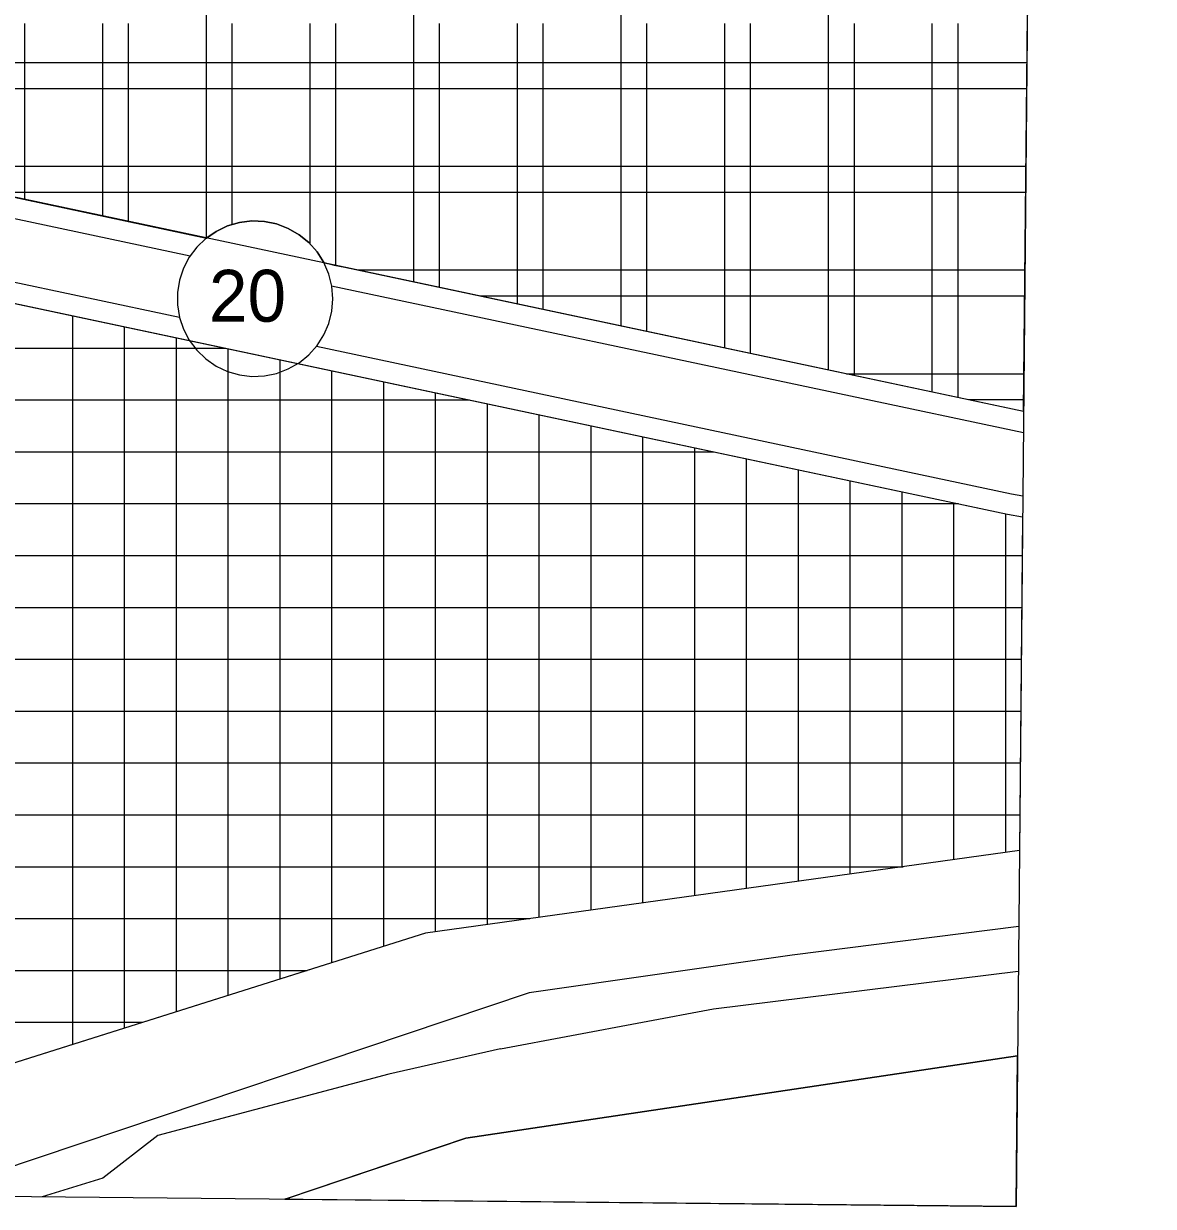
# Model space of a CAD drawing. Extents: x 427903 to 430077, y 4477233 to 4480385.
# Drawn here: x 429832.6 to 430050.5, y 4477233 to 4477461.1 of the extents above; entities that cross this region are included whole.
import ezdxf

# ---------------------------------------------------------------- set-up
doc = ezdxf.new("R2010")
doc.units = 0
for name, color, linetype in [('ADA', 7, 'Continuous'), ('ADAKENARI', 7, 'Continuous'), ('KALDIRIM', 7, 'Continuous'), ('KD_DAIRE', 7, 'Continuous'), ('KD_YGEN', 7, 'Continuous'), ('PL_K_DEPOLAMA', 7, 'Continuous'), ('PL_K_K_D_K_C_A', 7, 'Continuous'), ('PL_K_TALI_IS_MRK', 7, 'Continuous'), ('PL_KÜÇÜK_SANAYİ_ALANI', 7, 'Continuous'), ('SıNıR', 7, 'Continuous'), ('TR_DEPOLAMAALAN', 7, 'Continuous'), ('TR_KONUTDISIKCA', 7, 'Continuous'), ('TR_TALIISMERK', 7, 'Continuous')]:
    doc.layers.add(name, color=color, linetype=linetype)

msp = doc.modelspace()

# ---------------------------------------------------------------- linework, layer by layer
at = {"layer": 'ADA'}
msp.add_line((429883.82, 4477234.41), (429883.82, 4477234.7), dxfattribs=at)
at = {"layer": 'ADAKENARI'}
for p, q in [((429657.7, 4477443.87), (430022.41, 4477366.53)), ((430025.5, 4477386.32), (429801.15, 4477433.9)), ((430022.41, 4477366.53), (430025.31, 4477366.01)), ((430024.7, 4477301.66), (429910.11, 4477285.75)), ((430024.56, 4477287.03), (429980.82, 4477281.45)), ((429910.11, 4477285.75), (429751.53, 4477235.7)), ((429980.82, 4477281.45), (429930.08, 4477274.19)), ((429965.64, 4477271.14), (430024.47, 4477278.38)), ((429930.08, 4477274.19), (429826.85, 4477239.57)), ((429924.56, 4477263.41), (429965.64, 4477271.14)), ((429924.56, 4477263.41), (429903.05, 4477258.56)), ((429917.92, 4477246.16), (430024.32, 4477262.09)), ((429903.05, 4477258.56), (429858.48, 4477246.7)), ((429858.48, 4477246.7), (429847.85, 4477238.49)), ((429882.98, 4477234.42), (429917.92, 4477246.16)), ((429847.85, 4477238.49), (429836.17, 4477234.88))]:
    msp.add_line(p, q, dxfattribs=at)
at = {"layer": 'KALDIRIM'}
for p, q in [((429659.8, 4477459.78), (429864.71, 4477416.33)), ((429652.69, 4477449.03), (429862.64, 4477404.5)), ((429892.01, 4477410.54), (430025.47, 4477382.24)), ((429889.09, 4477398.89), (430023.18, 4477370.45)), ((430023.18, 4477370.45), (430025.35, 4477370.07)), ((430023.18, 4477370.45), (430025.35, 4477370.07))]:
    msp.add_line(p, q, dxfattribs=at)
at = {"layer": 'KD_DAIRE'}
for p, q in [((429871.9, 4477422.08), (429869.72, 4477421.04)), ((429871.9, 4477422.08), (429869.72, 4477421.04)), ((429874.22, 4477422.75), (429871.9, 4477422.08)), ((429874.22, 4477422.75), (429871.9, 4477422.08)), ((429876.61, 4477423.04), (429874.22, 4477422.75)), ((429876.61, 4477423.04), (429874.22, 4477422.75)), ((429879.03, 4477422.94), (429876.61, 4477423.04)), ((429879.03, 4477422.94), (429876.61, 4477423.04)), ((429881.39, 4477422.46), (429879.03, 4477422.94)), ((429881.39, 4477422.46), (429879.03, 4477422.94)), ((429883.65, 4477421.6), (429881.39, 4477422.46)), ((429883.65, 4477421.6), (429881.39, 4477422.46)), ((429885.74, 4477420.4), (429883.65, 4477421.6)), ((429885.74, 4477420.4), (429883.65, 4477421.6)), ((429867.73, 4477419.67), (429865.99, 4477418)), ((429867.73, 4477419.67), (429865.99, 4477418)), ((429869.72, 4477421.04), (429867.73, 4477419.67)), ((429869.72, 4477421.04), (429867.73, 4477419.67)), ((429887.61, 4477418.87), (429885.74, 4477420.4)), ((429887.61, 4477418.87), (429885.74, 4477420.4)), ((429865.99, 4477418), (429864.54, 4477416.07)), ((429865.99, 4477418), (429864.54, 4477416.07)), ((429889.21, 4477417.06), (429887.61, 4477418.87)), ((429889.21, 4477417.06), (429887.61, 4477418.87)), ((429890.5, 4477415.02), (429889.21, 4477417.06)), ((429890.5, 4477415.02), (429889.21, 4477417.06)), ((429864.54, 4477416.07), (429863.42, 4477413.93)), ((429864.54, 4477416.07), (429863.42, 4477413.93)), ((429891.45, 4477412.8), (429890.5, 4477415.02)), ((429891.45, 4477412.8), (429890.5, 4477415.02)), ((429863.42, 4477413.93), (429862.65, 4477411.64)), ((429863.42, 4477413.93), (429862.65, 4477411.64)), ((429892.02, 4477410.46), (429891.45, 4477412.8)), ((429892.02, 4477410.46), (429891.45, 4477412.8)), ((429862.65, 4477411.64), (429862.27, 4477409.26)), ((429862.65, 4477411.64), (429862.27, 4477409.26)), ((429892.22, 4477408.05), (429892.02, 4477410.46)), ((429892.22, 4477408.05), (429892.02, 4477410.46)), ((429862.27, 4477409.26), (429862.27, 4477406.85)), ((429862.27, 4477409.26), (429862.27, 4477406.85)), ((429892.02, 4477405.65), (429892.22, 4477408.05)), ((429892.02, 4477405.65), (429892.22, 4477408.05)), ((429892.22, 4477408.05), (429892.22, 4477408.05)), ((429892.22, 4477408.05), (429892.22, 4477408.05)), ((429862.27, 4477406.85), (429862.65, 4477404.46)), ((429862.27, 4477406.85), (429862.65, 4477404.46)), ((429891.45, 4477403.3), (429892.02, 4477405.65)), ((429891.45, 4477403.3), (429892.02, 4477405.65)), ((429862.65, 4477404.46), (429863.42, 4477402.17)), ((429862.65, 4477404.46), (429863.42, 4477402.17)), ((429890.5, 4477401.08), (429891.45, 4477403.3)), ((429890.5, 4477401.08), (429891.45, 4477403.3)), ((429863.42, 4477402.17), (429864.54, 4477400.04)), ((429863.42, 4477402.17), (429864.54, 4477400.04)), ((429889.21, 4477399.04), (429890.5, 4477401.08)), ((429889.21, 4477399.04), (429890.5, 4477401.08)), ((429864.54, 4477400.04), (429865.99, 4477398.11)), ((429864.54, 4477400.04), (429865.99, 4477398.11)), ((429887.61, 4477397.23), (429889.21, 4477399.04)), ((429887.61, 4477397.23), (429889.21, 4477399.04)), ((429865.99, 4477398.11), (429867.73, 4477396.43)), ((429865.99, 4477398.11), (429867.73, 4477396.43)), ((429867.73, 4477396.43), (429869.72, 4477395.06)), ((429867.73, 4477396.43), (429869.72, 4477395.06)), ((429885.74, 4477395.71), (429887.61, 4477397.23)), ((429885.74, 4477395.71), (429887.61, 4477397.23)), ((429869.72, 4477395.06), (429871.9, 4477394.03)), ((429869.72, 4477395.06), (429871.9, 4477394.03)), ((429881.39, 4477393.64), (429883.65, 4477394.5)), ((429881.39, 4477393.64), (429883.65, 4477394.5)), ((429883.65, 4477394.5), (429885.74, 4477395.71)), ((429883.65, 4477394.5), (429885.74, 4477395.71)), ((429871.9, 4477394.03), (429874.22, 4477393.36)), ((429871.9, 4477394.03), (429874.22, 4477393.36)), ((429874.22, 4477393.36), (429876.61, 4477393.06)), ((429874.22, 4477393.36), (429876.61, 4477393.06)), ((429876.61, 4477393.06), (429879.03, 4477393.16)), ((429876.61, 4477393.06), (429879.03, 4477393.16)), ((429879.03, 4477393.16), (429881.39, 4477393.64)), ((429879.03, 4477393.16), (429881.39, 4477393.64))]:
    msp.add_line(p, q, dxfattribs=at)
at = {"layer": 'PL_K_DEPOLAMA'}
for points in [[(430025.5, 4477386.34), (430026.54, 4477494.77)], [(429801.15, 4477433.9), (429867.85, 4477419.75), (429869.72, 4477421.04), (429871.9, 4477422.08), (429874.22, 4477422.75), (429876.61, 4477423.04), (429879.03, 4477422.94), (429881.39, 4477422.46), (429883.65, 4477421.6), (429885.74, 4477420.4), (429887.61, 4477418.87), (429889.21, 4477417.06), (429890.5, 4477415.02), (429890.54, 4477414.94), (429891.5, 4477414.76), (429892.51, 4477414.53), (429894.58, 4477414.11), (430025.5, 4477386.34)]]:
    msp.add_lwpolyline(points, dxfattribs=at)
at = {"layer": 'PL_K_K_D_K_C_A'}
for points in [[(430024.32, 4477262.09), (429917.92, 4477246.16), (429883.82, 4477234.7), (429883.82, 4477234.41)], [(429883.82, 4477234.41), (430024.04, 4477233.04), (430024.32, 4477262.09)]]:
    msp.add_lwpolyline(points, dxfattribs=at)
at = {"layer": 'PL_K_TALI_IS_MRK'}
for points in [[(429606.39, 4477237.12), (429622.51, 4477417.87), (429622.99, 4477421.13), (429623.83, 4477424.32), (429625.02, 4477427.39), (429626.56, 4477430.3), (429628.41, 4477433.03), (429630.55, 4477435.53), (429632.96, 4477437.77), (429635.61, 4477439.73), (429638.46, 4477441.38), (429641.48, 4477442.69), (429644.63, 4477443.66), (429647.87, 4477444.27), (429651.15, 4477444.51), (429654.44, 4477444.37), (429657.7, 4477443.87), (430022.41, 4477366.53), (430025.31, 4477366.01)], [(430025.31, 4477366.01), (430024.7, 4477301.66)], [(430024.7, 4477301.66), (429910.11, 4477285.75), (429751.53, 4477235.7)]]:
    msp.add_lwpolyline(points, dxfattribs=at)
at = {"layer": 'PL_KÜÇÜK_SANAYİ_ALANI'}
for points in [[(429883.82, 4477234.41), (429883.82, 4477234.7), (429882.98, 4477234.42)], [(429882.98, 4477234.42), (429883.82, 4477234.41)]]:
    msp.add_lwpolyline(points, dxfattribs=at)
at = {"layer": 'SıNıR'}
for p, q in [((430050.52, 4480009.82), (430024.04, 4477233.04)), ((430024.04, 4477233.04), (427902.58, 4477253.75))]:
    msp.add_line(p, q, dxfattribs=at)
at = {"layer": 'TR_DEPOLAMAALAN'}
for p, q in [((429867.84, 4477461.09), (429867.84, 4477501.09)), ((429907.84, 4477461.09), (429907.84, 4477501.09)), ((429947.84, 4477461.09), (429947.84, 4477501.09)), ((429987.84, 4477461.09), (429987.84, 4477501.09)), ((429832.84, 4477427.17), (429832.84, 4477461.09)), ((429847.84, 4477423.99), (429847.84, 4477461.09)), ((429852.84, 4477422.93), (429852.84, 4477461.09)), ((429867.84, 4477421.09), (429867.84, 4477461.09)), ((429872.84, 4477422.35), (429872.84, 4477461.09)), ((429887.84, 4477421.09), (429887.84, 4477461.09)), ((429892.84, 4477421.09), (429892.84, 4477461.09)), ((429907.84, 4477421.09), (429907.84, 4477461.09)), ((429912.84, 4477421.09), (429912.84, 4477461.09)), ((429927.84, 4477421.09), (429927.84, 4477461.09)), ((429932.84, 4477421.09), (429932.84, 4477461.09)), ((429947.84, 4477421.09), (429947.84, 4477461.09)), ((429952.84, 4477421.09), (429952.84, 4477461.09)), ((429967.84, 4477421.09), (429967.84, 4477461.09)), ((429972.84, 4477421.09), (429972.84, 4477461.09)), ((429987.84, 4477421.09), (429987.84, 4477461.09)), ((429992.84, 4477421.09), (429992.84, 4477461.09)), ((430007.84, 4477421.09), (430007.84, 4477461.09)), ((430012.84, 4477421.09), (430012.84, 4477461.09)), ((429807.02, 4477453.59), (429840.34, 4477453.59)), ((429840.34, 4477453.59), (429880.34, 4477453.59)), ((429880.34, 4477453.59), (429920.34, 4477453.59)), ((429920.34, 4477453.59), (429960.34, 4477453.59)), ((429960.34, 4477453.59), (430000.34, 4477453.59)), ((430000.34, 4477453.59), (430026.15, 4477453.59)), ((429805.53, 4477448.59), (430026.1, 4477448.59)), ((429802.6, 4477433.59), (429840.34, 4477433.59)), ((429840.34, 4477433.59), (429880.34, 4477433.59)), ((429880.34, 4477433.59), (429920.34, 4477433.59)), ((429920.34, 4477433.59), (429960.34, 4477433.59)), ((429960.34, 4477433.59), (430000.34, 4477433.59)), ((430000.34, 4477433.59), (430025.95, 4477433.59)), ((429826.18, 4477428.59), (430025.91, 4477428.59)), ((429867.84, 4477419.75), (429867.84, 4477421.09)), ((429867.84, 4477419.75), (429867.84, 4477421.09)), ((429867.84, 4477419.75), (429867.84, 4477421.09)), ((429887.84, 4477418.6), (429887.84, 4477421.09)), ((429887.84, 4477418.6), (429887.84, 4477421.09)), ((429887.84, 4477418.6), (429887.84, 4477421.09)), ((429892.84, 4477414.47), (429892.84, 4477421.09)), ((429892.84, 4477414.47), (429892.84, 4477421.09)), ((429892.84, 4477414.47), (429892.84, 4477421.09)), ((429907.84, 4477411.3), (429907.84, 4477421.09)), ((429912.84, 4477410.24), (429912.84, 4477421.09)), ((429927.84, 4477407.05), (429927.84, 4477421.09)), ((429932.84, 4477405.99), (429932.84, 4477421.09)), ((429947.84, 4477402.81), (429947.84, 4477421.09)), ((429952.84, 4477401.75), (429952.84, 4477421.09)), ((429967.84, 4477398.57), (429967.84, 4477421.09)), ((429972.84, 4477397.51), (429972.84, 4477421.09)), ((429987.84, 4477394.33), (429987.84, 4477421.09)), ((429992.84, 4477393.26), (429992.84, 4477421.09)), ((430007.84, 4477390.08), (430007.84, 4477421.09)), ((430012.84, 4477389.02), (430012.84, 4477421.09)), ((429897.05, 4477413.59), (429920.34, 4477413.59)), ((429920.34, 4477413.59), (429960.34, 4477413.59)), ((429960.34, 4477413.59), (430000.34, 4477413.59)), ((430000.34, 4477413.59), (430025.76, 4477413.59)), ((429920.62, 4477408.59), (430025.72, 4477408.59)), ((429991.33, 4477393.59), (430000.34, 4477393.59)), ((430000.34, 4477393.59), (430025.57, 4477393.59)), ((430014.89, 4477388.59), (430025.53, 4477388.59))]:
    msp.add_line(p, q, dxfattribs=at)
at = {"layer": 'TR_KONUTDISIKCA'}
for points in [[(430024.32, 4477262.09), (429917.92, 4477246.16), (429883.82, 4477234.7), (429883.82, 4477234.41)], [(429883.82, 4477234.41), (430024.04, 4477233.04), (430024.32, 4477262.09)], [(430024.32, 4477262.09), (429917.92, 4477246.16), (429883.82, 4477234.7), (429883.82, 4477234.41)], [(429883.82, 4477234.41), (430024.04, 4477233.04), (430024.32, 4477262.09)]]:
    msp.add_lwpolyline(points, dxfattribs=at)
at = {"layer": 'TR_TALIISMERK'}
for p, q in [((429842.05, 4477264.27), (429842.05, 4477404.78)), ((429852.05, 4477267.42), (429852.05, 4477402.66)), ((429862.05, 4477270.58), (429862.05, 4477400.54)), ((429620.79, 4477398.54), (429871.47, 4477398.54)), ((429872.05, 4477273.73), (429872.05, 4477398.41)), ((429882.05, 4477276.89), (429882.05, 4477396.29)), ((429892.05, 4477280.05), (429892.05, 4477394.17)), ((429902.05, 4477283.2), (429902.05, 4477392.05)), ((429912.05, 4477286.01), (429912.05, 4477389.93)), ((429619.9, 4477388.54), (429918.63, 4477388.54)), ((429922.05, 4477287.4), (429922.05, 4477387.81)), ((429932.05, 4477288.79), (429932.05, 4477385.69)), ((429942.05, 4477290.18), (429942.05, 4477383.57)), ((429952.05, 4477291.57), (429952.05, 4477381.45)), ((429619, 4477378.54), (429965.78, 4477378.54)), ((429962.05, 4477292.96), (429962.05, 4477379.33)), ((429972.05, 4477294.35), (429972.05, 4477377.21)), ((429982.05, 4477295.74), (429982.05, 4477375.09)), ((429992.05, 4477297.12), (429992.05, 4477372.97)), ((430002.05, 4477298.51), (430002.05, 4477370.85)), ((429618.11, 4477368.54), (430012.93, 4477368.54)), ((430012.05, 4477299.9), (430012.05, 4477368.72)), ((430022.05, 4477301.29), (430022.05, 4477366.6)), ((429617.22, 4477358.54), (430025.24, 4477358.54)), ((429616.33, 4477348.54), (430025.14, 4477348.54)), ((429615.44, 4477338.54), (430025.05, 4477338.54)), ((429614.54, 4477328.54), (430024.95, 4477328.54)), ((429683.03, 4477318.54), (430024.86, 4477318.54)), ((429682.02, 4477308.54), (430024.76, 4477308.54)), ((429681.02, 4477298.54), (430002.23, 4477298.54)), ((429680.01, 4477288.54), (429930.23, 4477288.54)), ((429610.08, 4477278.54), (429887.27, 4477278.54)), ((429609.19, 4477268.54), (429855.58, 4477268.54))]:
    msp.add_line(p, q, dxfattribs=at)

# ---------------------------------------------------------------- texts
at = {"layer": 'KD_YGEN'}
msp.add_text('20', height=10, dxfattribs=at).set_placement((429868.34, 4477403.62))
msp.add_text('20', height=10, dxfattribs=at).set_placement((429868.34, 4477403.62))

doc.saveas('drawing.dxf')
